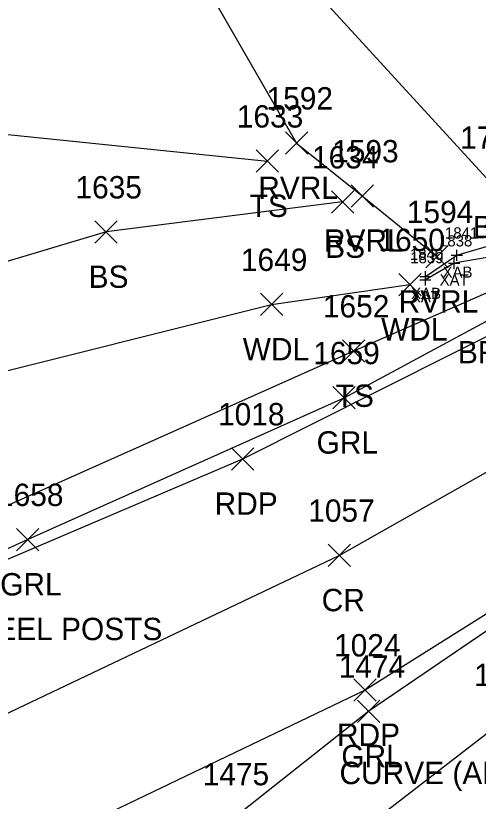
# Model space of a CAD drawing. Extents: x 1633660 to 1636532, y 388643 to 392631.
# Drawn here: x 1634396.6 to 1634438, y 388911.8 to 388982.1 of the extents above; entities that cross this region are included whole.
import ezdxf

# ---------------------------------------------------------------- set-up
doc = ezdxf.new("R2010")
doc.units = 0
for name, color, linetype in [('B_A', 7, 'Continuous'), ('B_I', 7, 'Continuous'), ('B_TIC', 7, 'Continuous'), ('BSUBM', 7, 'Continuous'), ('L_A', 7, 'Continuous'), ('L_I', 7, 'Continuous'), ('L_TIC', 7, 'Continuous'), ('LAWA', 7, 'Continuous'), ('LAWE', 7, 'Continuous'), ('LELB', 7, 'Continuous'), ('P_A', 7, 'Continuous'), ('P_I', 7, 'Continuous'), ('P_TIC', 7, 'Continuous'), ('PET', 7, 'Continuous'), ('PRC', 7, 'Continuous'), ('R_A', 7, 'Continuous'), ('R_C', 7, 'Continuous'), ('R_I', 7, 'Continuous'), ('R_TIC', 7, 'Continuous'), ('RGR', 7, 'Continuous'), ('S_C', 7, 'Continuous')]:
    doc.layers.add(name, color=color, linetype=linetype)

msp = doc.modelspace()

# ---------------------------------------------------------------- linework, layer by layer
at = {"layer": 'B_TIC'}
for p, q in [((1634436.131, 388960.642), (1634436.207, 388960.642)), ((1634435.884, 388959.935), (1634435.96, 388959.935)), ((1634433.311, 388958.436), (1634433.387, 388958.436)), ((1634433.316, 388958.737), (1634433.391, 388958.737))]:
    msp.add_line(p, q, dxfattribs=at)
for points in [[(1634436.128, 388960.142), (1634436.128, 388961.142)], [(1634435.628, 388960.642), (1634436.628, 388960.642)], [(1634435.881, 388959.435), (1634435.881, 388960.435)], [(1634435.381, 388959.935), (1634436.381, 388959.935)], [(1634433.312, 388958.237), (1634433.312, 388959.237)], [(1634432.808, 388958.436), (1634433.808, 388958.436)], [(1634432.812, 388958.737), (1634433.812, 388958.737)], [(1634433.308, 388957.936), (1634433.308, 388958.936)]]:
    msp.add_lwpolyline(points, dxfattribs=at)
at = {"layer": 'BSUBM'}
for points in [[(1634433.312, 388958.737), (1634436.128, 388960.642), (1634441.535, 388962.249), (1634446.395, 388963.412), (1634447.015, 388962.993), (1634484.967, 388957.086), (1634484.455, 388945.628)], [(1634449.803, 388962.133), (1634447.709, 388961.965), (1634435.881, 388959.935), (1634433.308, 388958.436)]]:
    msp.add_lwpolyline(points, dxfattribs=at)
at = {"layer": 'L_TIC'}
for points in [[(1634420.785, 388969.689), (1634422.785, 388971.689)], [(1634422.785, 388969.689), (1634420.785, 388971.689)], [(1634418.171, 388968.074), (1634420.171, 388970.074)], [(1634420.171, 388968.074), (1634418.171, 388970.074)], [(1634426.66, 388964.96), (1634428.66, 388966.96)], [(1634428.66, 388964.96), (1634426.66, 388966.96)], [(1634424.899, 388964.415), (1634426.899, 388966.415)], [(1634426.899, 388964.415), (1634424.899, 388966.415)], [(1634403.729, 388961.731), (1634405.729, 388963.731)], [(1634405.729, 388961.731), (1634403.729, 388963.731)], [(1634433.345, 388959.523), (1634435.345, 388961.523)], [(1634435.345, 388959.523), (1634433.345, 388961.523)], [(1634430.931, 388957.02), (1634432.931, 388959.02)], [(1634432.931, 388957.02), (1634430.931, 388959.02)], [(1634418.547, 388955.244), (1634420.547, 388957.244)], [(1634420.547, 388955.244), (1634418.547, 388957.244)], [(1634425.877, 388951.081), (1634427.877, 388953.081)], [(1634427.877, 388951.081), (1634425.877, 388953.081)]]:
    msp.add_lwpolyline(points, dxfattribs=at)
at = {"layer": 'LAWA'}
msp.add_lwpolyline([(1634029.515, 388906.746), (1634042.751, 388866.199), (1634043.288, 388851.863), (1634059.731, 388819.64), (1634086.073, 388831.906), (1634132.498, 388845.488), (1634141.644, 388844.494), (1634171.777, 388858.914), (1634210.319, 388873.396), (1634220.65, 388882.429), (1634241.672, 388885.398), (1634275.369, 388895.766), (1634312.677, 388911.322), (1634346.589, 388927.337), (1634362.703, 388937.8), (1634391.494, 388949.242), (1634419.547, 388956.244), (1634431.931, 388958.02)], dxfattribs=at)
at = {"layer": 'LAWE'}
msp.add_lwpolyline([(1634146.067, 388910.131), (1634157.514, 388906.82), (1634173.76, 388910.288), (1634198.371, 388919.709), (1634216.389, 388918.218), (1634229.125, 388935.263), (1634227.797, 388943.9), (1634246.122, 388965.868), (1634248.241, 388978.316), (1634283.084, 388994.346), (1634319.088, 389007.074), (1634380.979, 389013.992), (1634391.621, 389015.991), (1634409.167, 388992.61), (1634421.785, 388970.689), (1634427.66, 388965.96), (1634434.345, 388960.523)], dxfattribs=at)
at = {"layer": 'LELB'}
for points in [[(1634311.937, 389011.727), (1634343.3, 389019.171), (1634362.418, 389022.606), (1634391.71, 389019.285), (1634408.613, 389006.323), (1634418.168, 388990.077), (1634439.116, 388967.173)], [(1634425.899, 388965.415), (1634404.729, 388962.731), (1634362.757, 388950.178), (1634339.254, 388960.693), (1634329.502, 388983.651)], [(1634390.989, 388971.946), (1634419.171, 388969.074)], [(1634445.582, 388960.226), (1634426.877, 388952.081), (1634393.484, 388937.195), (1634364.772, 388929.813), (1634350.49, 388919.544), (1634324.395, 388908.277), (1634285.496, 388891.779), (1634241.121, 388873.713), (1634233.64, 388876.293)], [(1634125.579, 388742.686), (1634122.377, 388746.523), (1634122.379, 388759.174), (1634119.847, 388773.411), (1634127.606, 388794.705), (1634159.932, 388808.1), (1634199.649, 388823.276), (1634240.013, 388839.132), (1634282.637, 388856.778), (1634322.867, 388872.904), (1634357.402, 388883.596), (1634392.968, 388895.749), (1634413.992, 388898.724), (1634440.42, 388919.1), (1634461.601, 388936.25), (1634480.462, 388947.827), (1634480.68, 388954.277)]]:
    msp.add_lwpolyline(points, dxfattribs=at)
at = {"layer": 'P_TIC'}
for points in [[(1634415.956, 388941.424), (1634417.956, 388943.424)], [(1634417.956, 388941.424), (1634415.956, 388943.424)], [(1634424.595, 388932.799), (1634426.595, 388934.799)], [(1634426.595, 388932.799), (1634424.595, 388934.799)], [(1634426.909, 388920.751), (1634428.909, 388922.751)], [(1634428.909, 388920.751), (1634426.909, 388922.751)]]:
    msp.add_lwpolyline(points, dxfattribs=at)
at = {"layer": 'PET'}
msp.add_lwpolyline([(1634182.589, 388846.73), (1634235.607, 388867.857), (1634289.807, 388889.547), (1634340.226, 388910.316), (1634383.943, 388928.36), (1634416.956, 388942.424), (1634441.986, 388954.985), (1634450.019, 388959.853), (1634465.24, 388958.085), (1634480.348, 388956.008), (1634458.413, 388940.869), (1634427.909, 388921.751), (1634384.731, 388901.048), (1634334.49, 388879.365), (1634279.866, 388857.153), (1634233.656, 388838.288), (1634176.136, 388816.11)], dxfattribs=at)
at = {"layer": 'PRC'}
msp.add_lwpolyline([(1633685.214, 388740.891), (1633722.466, 388753.089), (1633765.947, 388761.743), (1633808.839, 388766.445), (1633860.632, 388768.049), (1633911.929, 388769.082), (1633965.446, 388772.582), (1634019.676, 388781.056), (1634071.374, 388793.875), (1634111.14, 388806.365), (1634160.922, 388824.059), (1634207.926, 388842.024), (1634253.706, 388860.359), (1634302.739, 388880.25), (1634347.864, 388899.141), (1634390.053, 388916.892), (1634425.595, 388933.799), (1634443.268, 388943.766), (1634464.462, 388957.565)], dxfattribs=at)
at = {"layer": 'R_TIC'}
for points in [[(1634425.027, 388946.9), (1634427.027, 388948.9)], [(1634427.027, 388946.9), (1634425.027, 388948.9)], [(1634396.708, 388934.211), (1634398.708, 388936.211)], [(1634398.708, 388934.211), (1634396.708, 388936.211)], [(1634427.243, 388918.846), (1634429.243, 388920.846)], [(1634429.243, 388918.846), (1634427.243, 388920.846)]]:
    msp.add_lwpolyline(points, dxfattribs=at)
at = {"layer": 'RGR'}
for points in [[(1634366.612, 388925.989), (1634383.781, 388928.869), (1634397.708, 388935.211), (1634426.027, 388947.9), (1634448.041, 388959.741)], [(1634480.3, 388955.361), (1634459.19, 388940.913), (1634428.243, 388919.846), (1634416.071, 388910.226), (1634409.286, 388902.118)]]:
    msp.add_lwpolyline(points, dxfattribs=at)

# ---------------------------------------------------------------- texts
at = {"layer": 'B_A'}
for s, p in [('XAB', (1634434.848, 388958.642)), ('XAT', (1634434.586, 388957.935)), ('XAB', (1634432.033, 388956.737)), ('XAT', (1634432.012, 388956.436))]:
    msp.add_text(s, height=1, dxfattribs=at).set_placement(p)
at = {"layer": 'B_I'}
for s, p in [('1841', (1634435.065, 388962.142)), ('1838', (1634434.534, 388961.435)), ('1840', (1634431.923, 388960.237)), ('1839', (1634431.957, 388959.936))]:
    msp.add_text(s, height=1, dxfattribs=at).set_placement(p)
at = {"layer": 'L_A'}
for s, p in [('RVRL', (1634418.352, 388965.689)), ('TS', (1634417.581, 388964.074)), ('BS', (1634437.557, 388962.173)), ('RVRL', (1634424.227, 388960.96)), ('BS', (1634424.34, 388960.415)), ('BS', (1634403.17, 388957.731)), ('RVRL', (1634430.912, 388955.523)), ('WDL', (1634429.349, 388953.02)), ('WDL', (1634416.964, 388951.244)), ('TS', (1634425.286, 388947.081))]:
    msp.add_text(s, height=2, dxfattribs=at).set_placement(p)
at = {"layer": 'L_I'}
for s, p in [('1592', (1634419.092, 388973.689)), ('1633', (1634416.431, 388972.074)), ('1723', (1634436.423, 388970.173)), ('1593', (1634424.967, 388968.96)), ('1634', (1634423.159, 388968.415)), ('1635', (1634401.989, 388965.731)), ('1594', (1634431.652, 388963.523)), ('1650', (1634429.104, 388961.02)), ('1649', (1634416.799, 388959.244)), ('1652', (1634424.137, 388955.081)), ('1467', (1634437.68, 388922.1))]:
    msp.add_text(s, height=2, dxfattribs=at).set_placement(p)
at = {"layer": 'P_A'}
for s, p in [('RDP', (1634414.444, 388937.424)), ('CR', (1634424.028, 388928.799)), ('RDP', (1634425.398, 388916.751))]:
    msp.add_text(s, height=2, dxfattribs=at).set_placement(p)
at = {"layer": 'P_I'}
for s, p in [('1018', (1634414.751, 388945.424)), ('1057', (1634422.824, 388936.799)), ('1024', (1634425.138, 388924.751))]:
    msp.add_text(s, height=2, dxfattribs=at).set_placement(p)
at = {"layer": 'R_A'}
for p in [(1634423.57, 388942.9), (1634395.251, 388930.211), (1634425.787, 388914.846)]:
    msp.add_text('GRL', height=2, dxfattribs=at).set_placement(p)
at = {"layer": 'R_C'}
msp.add_text('SGR W/ STEEL POSTS', height=2, dxfattribs=at).set_placement((1634380.936, 388926.211))
at = {"layer": 'R_I'}
for s, p in [('1659', (1634423.279, 388950.9)), ('1658', (1634394.968, 388938.211)), ('1474', (1634425.55, 388922.846)), ('1475', (1634413.378, 388913.226))]:
    msp.add_text(s, height=2, dxfattribs=at).set_placement(p)
at = {"layer": 'S_C'}
for s, p in [('BRIDGE WARNING', (1634436.222, 388950.978)), ('CURVE (ARROW LEFT)', (1634425.622, 388913.329))]:
    msp.add_text(s, height=2, dxfattribs=at).set_placement(p)

doc.saveas('drawing.dxf')
